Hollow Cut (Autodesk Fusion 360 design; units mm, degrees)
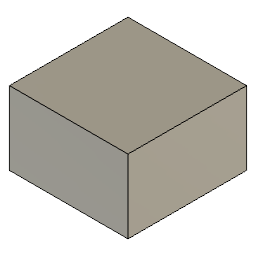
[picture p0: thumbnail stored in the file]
part number: 2025-09-27-23-07-06-343
sketch "Sketch1" plane through (0, 0, 0) normal (0, 0, 1) x axis (1, 0, 0)
  line L1 (17, 0) -> (0, 0)
  line L2 (17, 17) -> (17, 0)
  line L3 (0, 17) -> (17, 17)
  line L4 (0, 0) -> (0, 17)
  point P1 (0, 0)
  point P2 (0, 0)
  point P3 (17, 0)
  point P5 (0, 17)
  horizontal L1
  vertical L2
  horizontal L3
  vertical L4
  coincident P1 P2
  dimension "d1" distance P2 P3 = 17
  dimension "d2" distance P2 P5 = 17
extrude "Extrude1" new body sketch "Sketch1" along normal blind 10.53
